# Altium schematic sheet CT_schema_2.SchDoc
size 372 x 328 mm
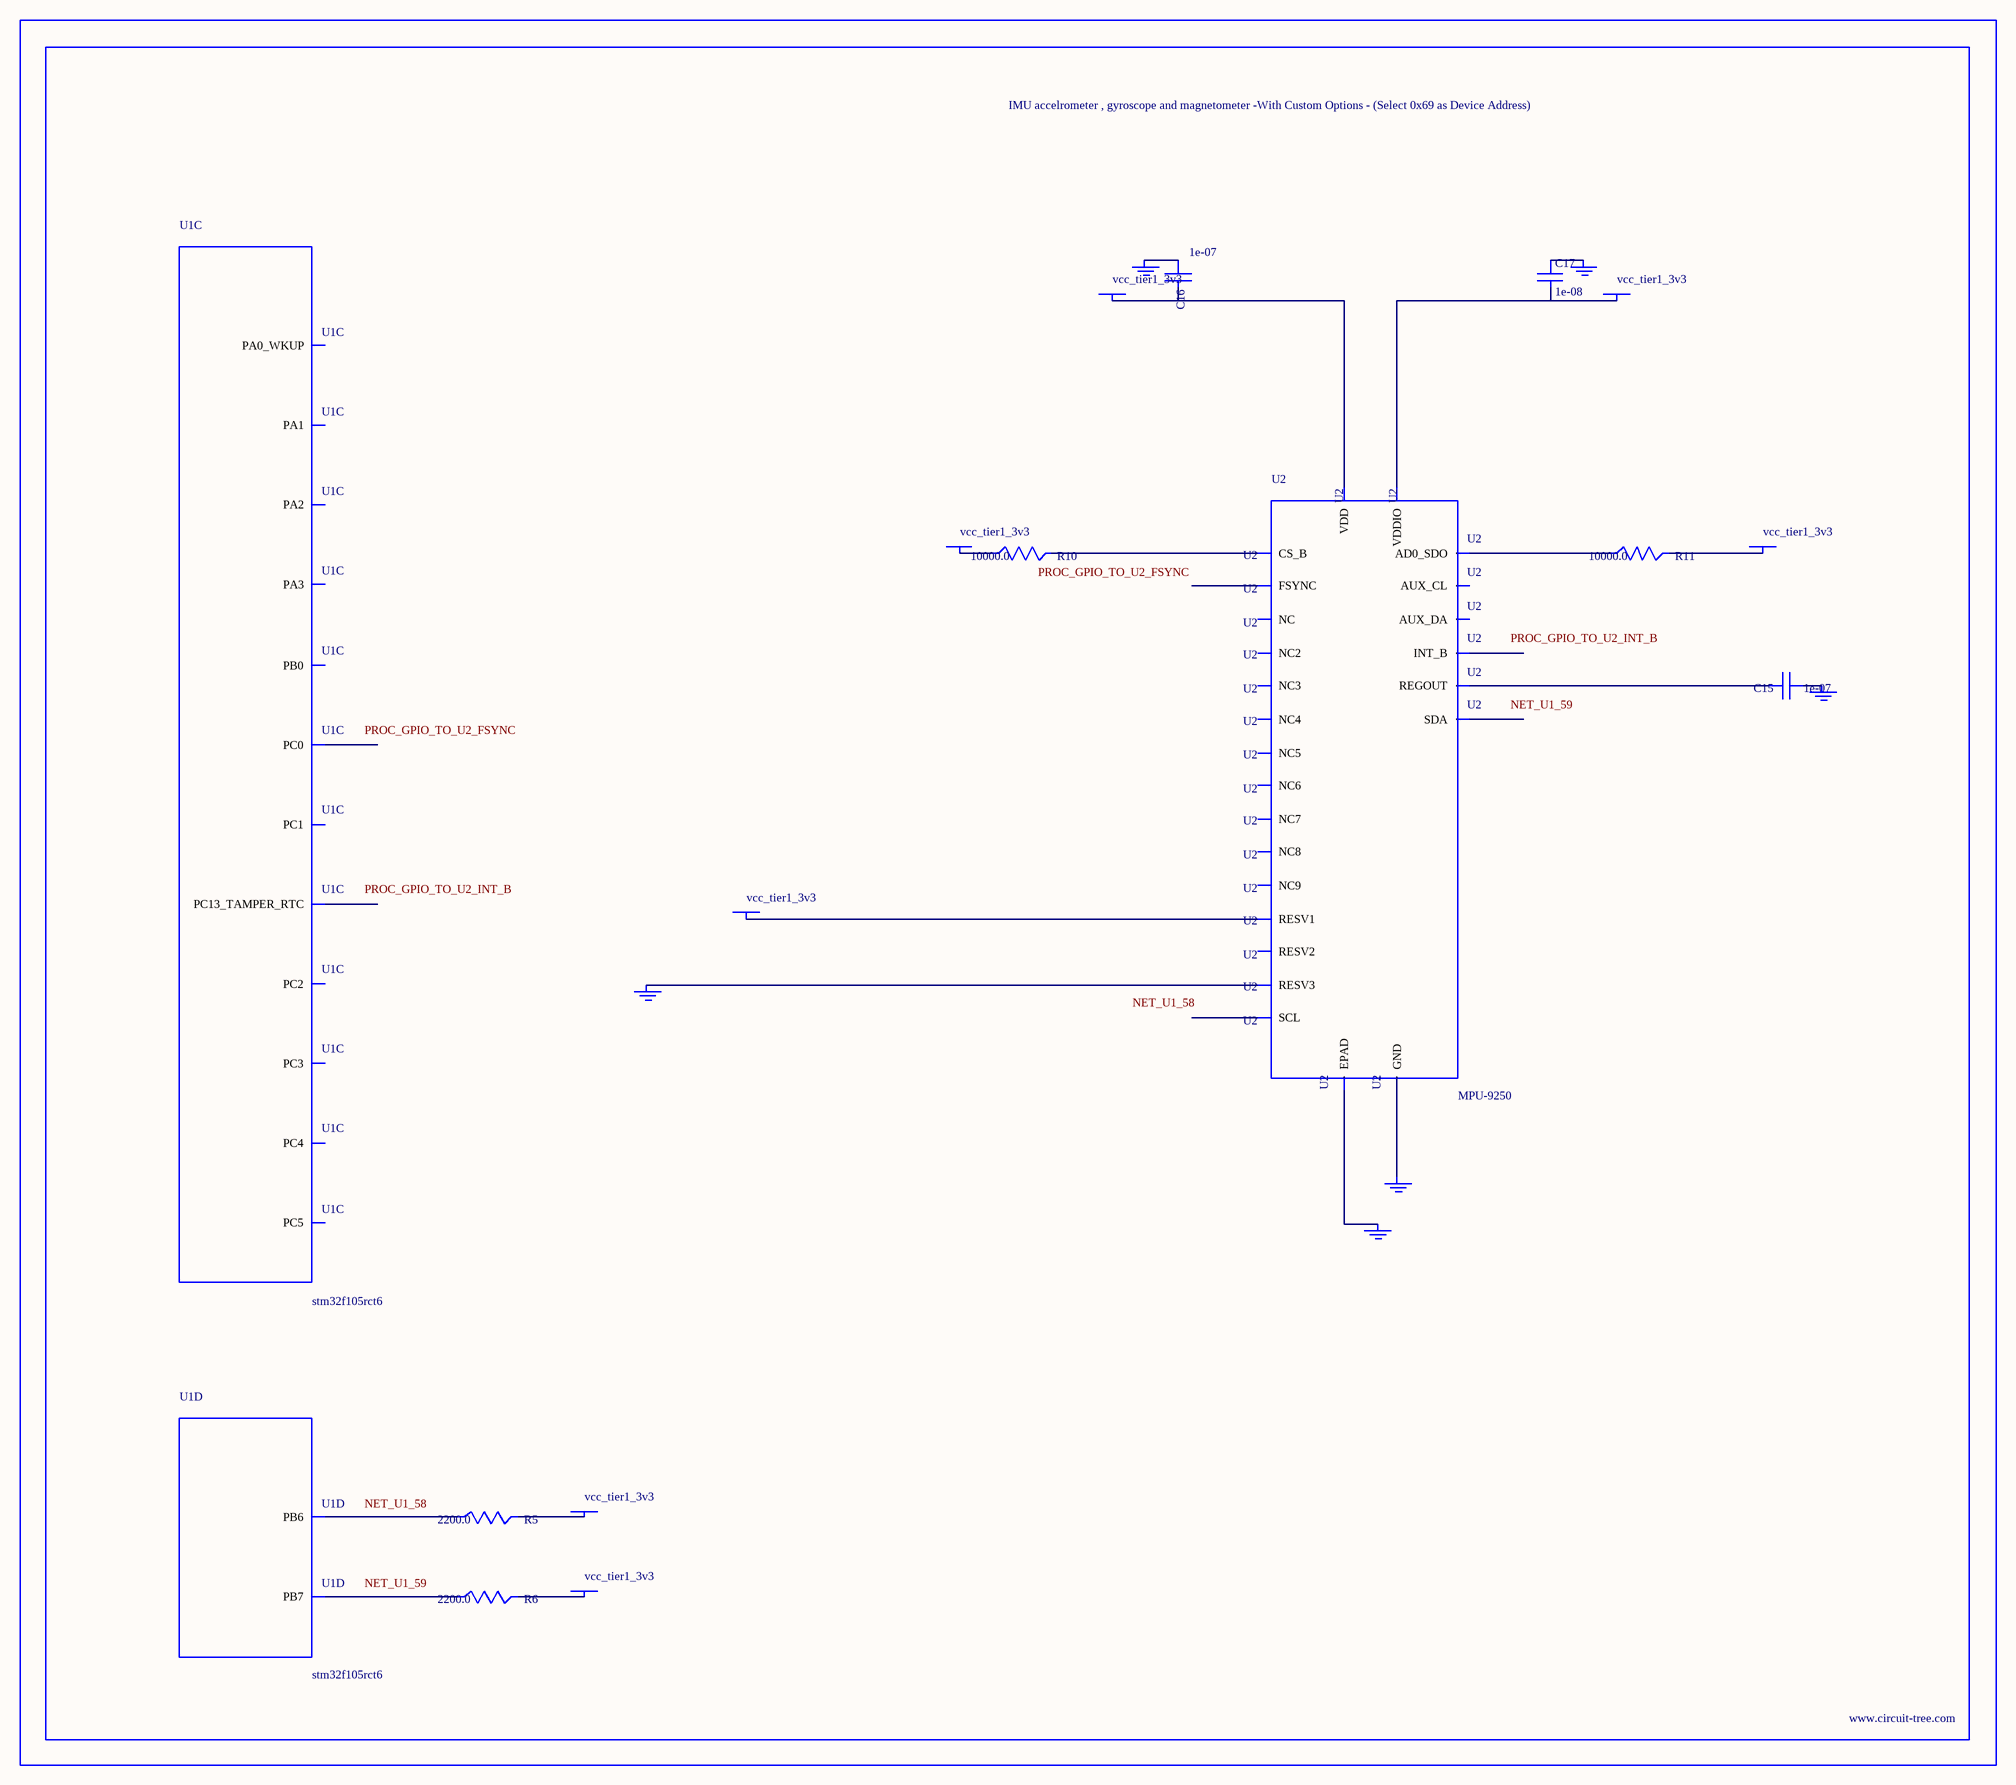
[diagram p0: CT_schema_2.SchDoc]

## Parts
BORDER1  (no value)
C15  1e-07  [C0402]
C16  1e-07  [C0402]
C17  1e-08  [C0402]
GND_INSTANCE_1_0  (no value)
GND_INSTANCE_1_1  (no value)
GND_INSTANCE_1_2  (no value)
GND_INSTANCE_1_3  (no value)
GND_INSTANCE_1_4  (no value)
GND_INSTANCE_1_5  (no value)
POWER_INSTANCE_1_0  vcc_tier1_3v3
POWER_INSTANCE_1_1  vcc_tier1_3v3
POWER_INSTANCE_1_2  vcc_tier1_3v3
POWER_INSTANCE_1_3  vcc_tier1_3v3
POWER_INSTANCE_1_4  vcc_tier1_3v3
POWER_INSTANCE_1_5  vcc_tier1_3v3
POWER_INSTANCE_1_6  vcc_tier1_3v3
R5  2200.0  [R0603]
R6  2200.0  [R0603]
R10  10000.0  [R0603]
R11  10000.0  [R0603]
U1  stm32f105rct6  [LQFP64]  (parts C,D of 7)
U2  MPU-9250  [QFN24_2]

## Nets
NetC15_1: C15.1 GND_INSTANCE_1_1.0(GND)
NetC15_2: C15.2 U2.10(REGOUT)
NetC16_1: C16.1 GND_INSTANCE_1_2.0(GND)
NetC16_2: C16.2 POWER_INSTANCE_1_3.0(PWR) U2.13(VDD)
NetC17_1: C17.1 GND_INSTANCE_1_0.0(GND)
NetC17_2: C17.2 POWER_INSTANCE_1_1.0(PWR) U2.8(VDDIO)
NetGND_INSTANCE_1_3_0: GND_INSTANCE_1_3.0(GND) U2.20(RESV3)
NetGND_INSTANCE_1_4_0: GND_INSTANCE_1_4.0(GND) U2.25(EPAD)
NetGND_INSTANCE_1_5_0: GND_INSTANCE_1_5.0(GND) U2.18(GND)
NetPOWER_INSTANCE_1_0_0: POWER_INSTANCE_1_0.0(PWR) U2.1(RESV1)
NetPOWER_INSTANCE_1_2_0: POWER_INSTANCE_1_2.0(PWR) R11.2
NetPOWER_INSTANCE_1_4_0: POWER_INSTANCE_1_4.0(PWR) R10.1
NetPOWER_INSTANCE_1_5_0: POWER_INSTANCE_1_5.0(PWR) R5.2
NetPOWER_INSTANCE_1_6_0: POWER_INSTANCE_1_6.0(PWR) R6.2
NetR5_1: R5.1 U1.58(PB6)
NetR6_1: R6.1 U1.59(PB7)
NetR10_2: R10.2 U2.22(CS_B)
NetR11_1: R11.1 U2.9(AD0_SDO)

Not connected (* = marked no-connect by the designer): U1 2(PC13_TAMPER_RTC) 8(PC0) 9(PC1) 10(PC2) 11(PC3) 14(PA0_WKUP) 15(PA1) 16(PA2) 17(PA3) 24(PC4) 25(PC5) 26(PB0); U2 2(NC) 3(NC2) 4(NC3) 5(NC4) 6(NC5) 7(AUX_CL) 11(FSYNC) 12(INT_B) 14(NC6) 15(NC7) 16(NC8) 17(NC9) 19(RESV2) 21(AUX_DA) 23(SCL) 24(SDA)

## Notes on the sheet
- Labels drawn without touching a wire or pin: NET_U1_58, NET_U1_59, PROC_GPIO_TO_U2_FSYNC, PROC_GPIO_TO_U2_INT_B

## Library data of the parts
BORDER1 = BORDER_PAGE1
C15 C16 = C0402C104K3RACTU
C17 = C0402C103K3RAC
GND_INSTANCE_1_0-GND_INSTANCE_1_5 = GND
POWER_INSTANCE_1_0-POWER_INSTANCE_1_6 = PWR
R5 R6 = RC0603JR-072K2L
R10 R11 = RC0603JR-0710KL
